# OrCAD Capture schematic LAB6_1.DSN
size A
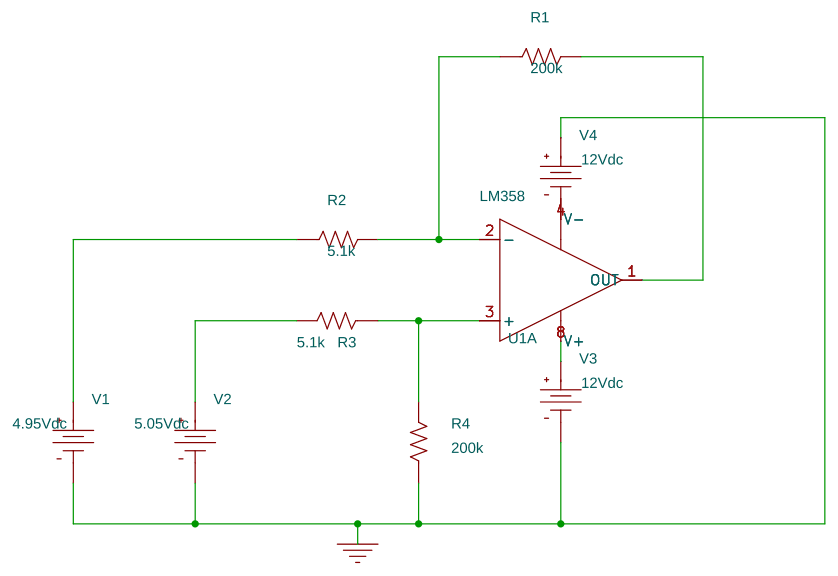
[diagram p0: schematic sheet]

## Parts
R1  200k  [AXRC05]
R2  5.1k  [AXRC05]
R3  5.1k  [AXRC05]
R4  200k  [AXRC05]
U1  LM358  [DIP1008W300L450]  (section A)
V1  VDC
V2  VDC
V3  VDC
V4  VDC

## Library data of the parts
R1-R4 = R
U1 = LM358
V1 = VDC: DC: 4.95Vdc
V2 = VDC: DC: 5.05Vdc
V3 V4 = VDC: DC: 12Vdc

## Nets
0: R4.1 V1.1(-) V2.1(-) V3.1(-) V4.0(+)
N00227: R1.2 U1.1(OUT)
N00239: R1.1 R2.2 U1.2(-)
N00260: R2.1 V1.0(+)
N00267: R3.2 V2.0(+)
N00274: R3.1 R4.2 U1.3(+)
N00445: U1.8(V+) V3.0(+)
N00709: U1.4(V-) V4.1(-)
